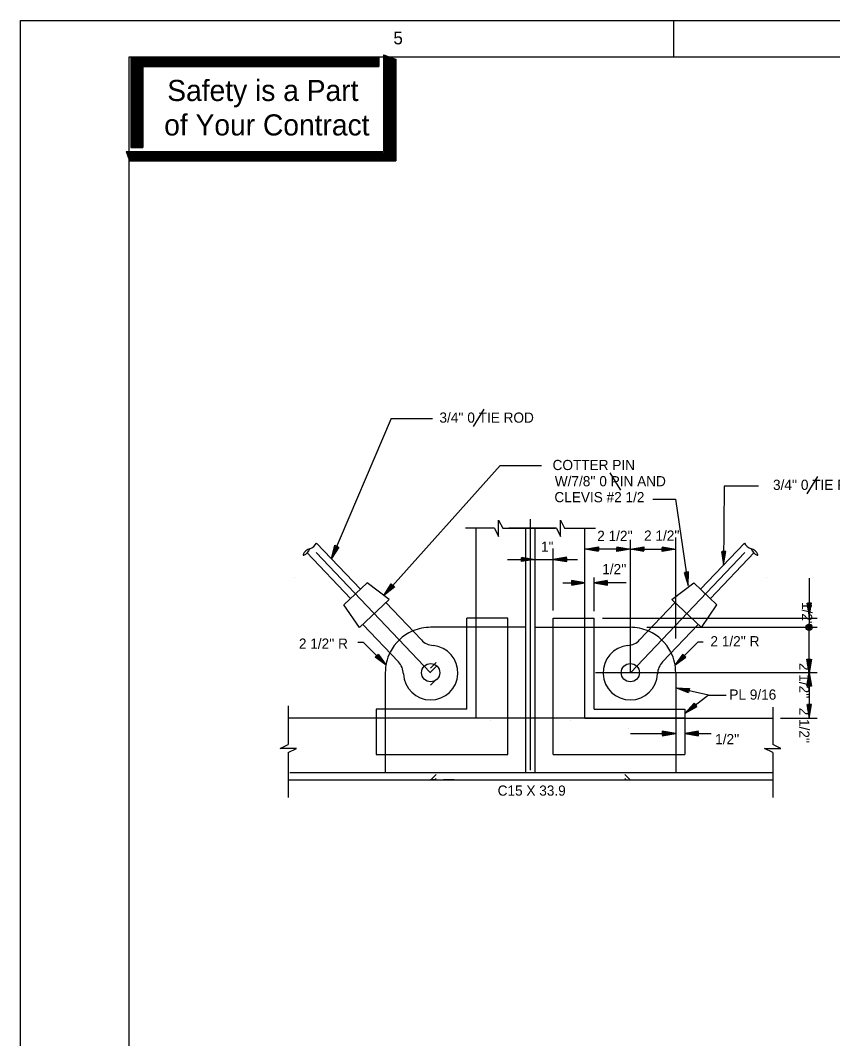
# Model space of a CAD drawing. Extents: x -0.4 to 13.5, y 0 to 9.5.
# Drawn here: x 0.125 to 3.853, y 4.787 to 9.458 of the extents above; entities that cross this region are included whole.
import ezdxf

# ---------------------------------------------------------------- set-up
doc = ezdxf.new("R2010")
doc.units = 0
for name, color, linetype in [('Level 1', 7, 'Continuous'), ('Level 13', 7, 'Continuous'), ('Level 25', 7, 'Continuous'), ('Level 3', 7, 'Continuous'), ('Level 50', 7, 'Continuous')]:
    doc.layers.add(name, color=color, linetype=linetype)

msp = doc.modelspace()

# ---------------------------------------------------------------- linework, layer by layer
at = {"layer": 'Level 1'}
for p, q in [((3.125, 9.2917), (3.125, 9.4583)), ((1.792, 9.3009), (1.792, 8.8562)), ((1.792, 9.3009), (1.8477, 9.2802)), ((1.7957, 9.2996), (1.7957, 8.8146)), ((1.8007, 9.2976), (1.8007, 8.8146)), ((0.632, 9.2886), (1.771, 9.2886)), ((0.632, 9.2886), (0.632, 8.8749)), ((0.632, 9.2832), (1.771, 9.2832)), ((0.632, 9.2782), (1.771, 9.2782)), ((0.632, 9.2729), (1.771, 9.2729)), ((0.632, 9.2676), (1.771, 9.2676)), ((0.632, 9.2626), (1.771, 9.2626)), ((0.632, 9.2572), (1.771, 9.2572)), ((0.632, 9.2522), (1.771, 9.2522)), ((0.6374, 9.2886), (0.6374, 8.8749)), ((0.6424, 9.2886), (0.6424, 8.8749)), ((0.6477, 9.2886), (0.6477, 8.8749)), ((0.6527, 9.2886), (0.6527, 8.8749)), ((0.658, 9.2886), (0.658, 8.8749)), ((0.6634, 9.2886), (0.6634, 8.8749)), ((0.6684, 9.2886), (0.6684, 8.8749)), ((0.6737, 9.2886), (0.6737, 8.8749)), ((0.679, 9.2886), (0.679, 8.8749)), ((0.684, 9.2886), (0.684, 8.8749)), ((1.771, 9.2886), (1.771, 9.2469)), ((1.806, 9.2956), (1.806, 8.8146)), ((1.8114, 9.2936), (1.8114, 8.8146)), ((1.8164, 9.2919), (1.8164, 8.8146)), ((1.8217, 9.2899), (1.8217, 8.8146)), ((1.8267, 9.2879), (1.8267, 8.8146)), ((1.832, 9.2859), (1.832, 8.8146)), ((1.8374, 9.2842), (1.8374, 8.8146)), ((1.8424, 9.2802), (1.8424, 8.8146)), ((1.8477, 9.2802), (1.8477, 8.8146)), ((0.6877, 9.2469), (1.771, 9.2469)), ((0.6877, 9.2469), (0.6877, 8.8749)), ((0.611, 8.8562), (1.792, 8.8562)), ((0.611, 8.8562), (0.6264, 8.8146)), ((0.613, 8.8509), (1.7957, 8.8509)), ((0.6147, 8.8459), (1.7957, 8.8459)), ((0.6167, 8.8406), (1.7957, 8.8406)), ((0.6187, 8.8352), (1.7957, 8.8352)), ((0.6207, 8.8302), (1.7957, 8.8302)), ((0.632, 8.8749), (0.6877, 8.8749)), ((0.6227, 8.8249), (1.7957, 8.8249)), ((0.6244, 8.8199), (1.7957, 8.8199)), ((0.6264, 8.8146), (1.8477, 8.8146)), ((2.2524, 7.6741), (2.2036, 7.5953)), ((2.8809, 7.3031), (2.8322, 7.3819)), ((3.7834, 7.3656), (3.7346, 7.2869)), ((2.3017, 7.1287), (2.1685, 7.1287)), ((2.3391, 7.1287), (2.5811, 7.1287)), ((2.5854, 7.1287), (2.3675, 7.1287)), ((2.6228, 7.1287), (2.7645, 7.1287)), ((2.9248, 7.0326), (2.7165, 7.0326)), ((2.9248, 7.0326), (3.1332, 7.0326)), ((2.3611, 6.9854), (2.4873, 6.9854)), ((2.4873, 6.9854), (2.6825, 6.9854)), ((2.6143, 6.8781), (2.7165, 6.8781)), ((2.9055, 6.8781), (2.7582, 6.8781)), ((2.7971, 6.7156), (3.7825, 6.7156)), ((2.9999, 6.674), (3.7825, 6.674)), ((3.7825, 6.4656), (2.7645, 6.4656)), ((3.6135, 6.2573), (3.7825, 6.2573)), ((2.9248, 6.1866), (3.1332, 6.1866)), ((3.1748, 6.1866), (3.2959, 6.1866))]:
    msp.add_line(p, q, dxfattribs=at)
for points in [[(0.125, 9.4583), (13.4583, 9.4583), (13.4583, 0.125), (0.125, 0.125)], [(0.625, 9.2917), (13.2917, 9.2917), (13.2917, 0.2917), (0.625, 0.2917)]]:
    msp.add_lwpolyline(points, close=True, dxfattribs=at)
at = {"layer": 'Level 13'}
for points in [[(2.3017, 7.1287), (2.3203, 7.0912), (2.3203, 7.1661), (2.3391, 7.1287)], [(2.5854, 7.1287), (2.604, 7.0912), (2.604, 7.1661), (2.6228, 7.1287)], [(1.3548, 6.0988), (1.3923, 6.1174), (1.3174, 6.1174), (1.3548, 6.1361)], [(3.5782, 6.0988), (3.5407, 6.1174), (3.6156, 6.1174), (3.5782, 6.1361)]]:
    msp.add_lwpolyline(points, dxfattribs=at)
for centre, radius, start, end in [((1.4387, 7.083), 0.051, 287.0106, 333.8095), ((3.4943, 7.083), 0.051, 206.1905, 252.9894), ((1.4249, 7.0069), 0.0025, 153.8112, 293.4241), ((1.4685, 6.9855), 0.051, 107.0106, 153.8112), ((1.4056, 7.0515), 0.051, 293.4241, 340.2247), ((3.5274, 7.0515), 0.051, 199.7753, 246.5759), ((3.4645, 6.9855), 0.051, 26.1888, 72.9894), ((3.5081, 7.0069), 0.0025, 246.5759, 26.1888)]:
    msp.add_arc(centre, radius, start, end, dxfattribs=at)
at = {"layer": 'Level 25'}
for p, q in [((1.8277, 7.6314), (1.5527, 6.9889)), ((1.8277, 7.6314), (2.0174, 7.6314)), ((2.3278, 7.4155), (1.7938, 6.8196)), ((2.3278, 7.4155), (2.5175, 7.4155)), ((2.4665, 6.0189), (2.4665, 7.1693)), ((2.2165, 6.2573), (2.2165, 7.1287)), ((2.4457, 6.0073), (2.4457, 7.1287)), ((2.4873, 6.0073), (2.4873, 7.1287)), ((2.7165, 6.2573), (2.7165, 7.1287)), ((1.6859, 6.8492), (1.4845, 7.0605)), ((2.9248, 6.4656), (2.9248, 7.0754)), ((3.1332, 6.6225), (3.1332, 7.0853)), ((3.2471, 6.8492), (3.4485, 7.0605)), ((1.6406, 6.8061), (1.4393, 7.0174)), ((2.0082, 6.4656), (1.4824, 7.0174)), ((2.5707, 6.7506), (2.5707, 7.0357)), ((2.9248, 6.4656), (3.4506, 7.0174)), ((3.2924, 6.8061), (3.4937, 7.0174)), ((1.3832, 6.9021), (1.3832, 6.9021)), ((1.7161, 6.8779), (1.6105, 6.7773)), ((1.8174, 6.8018), (1.7161, 6.8779)), ((2.7582, 6.7475), (2.7582, 6.9024)), ((3.1156, 6.8018), (3.2169, 6.8779)), ((3.2169, 6.8779), (3.3225, 6.7773)), ((3.5498, 6.9021), (3.5498, 6.9021)), ((3.7455, 6.8996), (3.7455, 6.6913)), ((1.6816, 6.6725), (1.6105, 6.7773)), ((1.8174, 6.8018), (1.6816, 6.6725)), ((1.9659, 6.6157), (1.8023, 6.7874)), ((2.9671, 6.6157), (3.1307, 6.7874)), ((3.1156, 6.8018), (3.2514, 6.6725)), ((3.2514, 6.6725), (3.3225, 6.7773)), ((1.8603, 6.5151), (1.6967, 6.6868)), ((2.1748, 6.299), (2.1748, 6.7156)), ((2.2165, 6.7156), (2.1748, 6.7156)), ((2.3623, 6.7156), (2.2165, 6.7156)), ((2.3623, 6.0906), (2.3623, 6.7156)), ((2.5707, 6.0906), (2.5707, 6.7156)), ((2.5707, 6.7156), (2.7165, 6.7156)), ((2.7165, 6.7156), (2.7582, 6.7156)), ((2.7582, 6.299), (2.7582, 6.7156)), ((3.0727, 6.5151), (3.2363, 6.6868)), ((3.7455, 6.483), (3.7455, 6.6913)), ((2.2165, 6.674), (2.0082, 6.674)), ((2.1748, 6.674), (2.0082, 6.674)), ((2.1748, 6.674), (2.1748, 6.674)), ((2.4457, 6.674), (2.1748, 6.674)), ((2.4873, 6.674), (2.7582, 6.674)), ((2.7165, 6.674), (2.9248, 6.674)), ((2.7582, 6.674), (2.7582, 6.674)), ((2.7582, 6.674), (2.9248, 6.674)), ((2.0343, 6.5128), (2.0082, 6.4868)), ((2.0343, 6.494), (2.0082, 6.4679)), ((1.7998, 6.4656), (1.7998, 6.299)), ((3.1332, 6.4656), (3.1332, 6.299)), ((3.7455, 6.483), (3.7455, 6.2573)), ((2.0343, 6.4351), (2.0082, 6.409)), ((3.2831, 6.3628), (3.1332, 6.3963)), ((3.2831, 6.3628), (3.1748, 6.2787)), ((3.2831, 6.3628), (3.3651, 6.3628)), ((1.3548, 6.3131), (1.3548, 6.1361)), ((3.5782, 6.3075), (3.5782, 6.1361)), ((2.1748, 6.299), (1.7582, 6.299)), ((1.7582, 6.299), (1.7582, 6.2503)), ((1.7998, 6.299), (1.7998, 6.0073)), ((2.7582, 6.299), (3.1748, 6.299)), ((3.1332, 6.299), (3.1332, 6.0073)), ((3.1748, 6.299), (3.1748, 6.2535)), ((2.7165, 6.2573), (1.3548, 6.2573)), ((2.2165, 6.2573), (1.7582, 6.2573)), ((1.7582, 6.2503), (1.7582, 6.0906)), ((2.2846, 6.2465), (2.2846, 6.2465)), ((2.6484, 6.2465), (2.6484, 6.2465)), ((2.7165, 6.2573), (3.5782, 6.2573)), ((3.1748, 6.2573), (2.7165, 6.2573)), ((3.1748, 6.2535), (3.1748, 6.0906)), ((2.9171, 6.2079), (2.9171, 6.2079)), ((1.3548, 6.0988), (1.3548, 5.8928)), ((1.7582, 6.0906), (2.3623, 6.0906)), ((2.5707, 6.0906), (3.1748, 6.0906)), ((3.5782, 6.0988), (3.5782, 5.8928)), ((1.3621, 6.0073), (3.5782, 6.0073)), ((2.0343, 5.9989), (2.0087, 5.9734)), ((2.0343, 5.9801), (2.0276, 5.9734)), ((2.8988, 5.9989), (2.9243, 5.9734)), ((2.8988, 5.9801), (2.9054, 5.9734)), ((1.3548, 5.974), (3.5782, 5.974)), ((2.0343, 5.9734), (2.0082, 5.9734)), ((2.1165, 5.9734), (2.0666, 5.9734)), ((2.1029, 5.9734), (2.1029, 5.9734)), ((2.8165, 5.9734), (2.8665, 5.9734)), ((2.8301, 5.9734), (2.8301, 5.9734)), ((2.8988, 5.9734), (2.9248, 5.9734))]:
    msp.add_line(p, q, dxfattribs=at)
for centre in [(2.0082, 6.4656), (2.9248, 6.4656)]:
    msp.add_circle(centre, 0.0417, dxfattribs=at)
for centre, radius, start, end in [((2.0082, 6.4656), 0.2083, 113.9464, 153.1723), ((2.0082, 6.4656), 0.2083, 90, 113.2322), ((2.9248, 6.4656), 0.2083, 66.7678, 90), ((2.9248, 6.4656), 0.2083, 26.8277, 66.0536), ((2.0082, 6.4656), 0.125, 182.1999, 85.0192), ((2.0263, 6.6732), 0.0833, 223.6094, 265.0192), ((2.9248, 6.4656), 0.125, 94.9808, 357.8001), ((2.9068, 6.6732), 0.0833, 274.9808, 316.3906), ((2.0082, 6.4656), 0.2083, 153.5287, 180), ((2.9248, 6.4656), 0.2083, 0, 26.4713), ((1.8, 6.4576), 0.0833, 2.1999, 43.6109), ((3.133, 6.4576), 0.0833, 136.3891, 177.8001)]:
    msp.add_arc(centre, radius, start, end, dxfattribs=at)
at = {"layer": 'Level 3'}
for p, q in [((3.3527, 6.9772), (3.3527, 6.9772)), ((3.3526, 6.9598), (3.3526, 6.9598)), ((3.188, 6.8824), (3.188, 6.8824)), ((3.1905, 6.8653), (3.1905, 6.8653)), ((1.7922, 6.5119), (1.7922, 6.5119)), ((1.8044, 6.4996), (1.8044, 6.4996)), ((3.1286, 6.4996), (3.1286, 6.4996)), ((3.1408, 6.5119), (3.1408, 6.5119))]:
    msp.add_line(p, q, dxfattribs=at)
for points in [[(3.5129, 7.3221), (3.3553, 7.3221), (3.3526, 6.9598)], [(3.0285, 7.2619), (3.1317, 7.2619), (3.1905, 6.8653)], [(3.3427, 7.0222), (3.3526, 6.9598), (3.3634, 7.0221), (3.3457, 7.0222), (3.3527, 6.9772), (3.36, 7.0194), (3.3487, 7.0195), (3.3528, 6.9938), (3.3567, 7.0168), (3.352, 7.0168), (3.353, 7.0112)], [(3.1712, 6.9254), (3.1905, 6.8653), (3.1916, 6.9284), (3.1741, 6.9258), (3.188, 6.8824), (3.1887, 6.9253), (3.1775, 6.9236), (3.1856, 6.8989), (3.1858, 6.9222), (3.1812, 6.9215), (3.183, 6.916)], [(1.6743, 6.605), (1.6991, 6.605), (1.8044, 6.4996)], [(3.2587, 6.605), (3.2339, 6.605), (3.1286, 6.4996)], [(1.7677, 6.551), (1.8044, 6.4996), (1.7531, 6.5364), (1.7656, 6.5489), (1.7922, 6.5119), (1.7573, 6.5368), (1.7653, 6.5449), (1.7804, 6.5236), (1.7615, 6.5373), (1.7648, 6.5406), (1.7681, 6.5359)], [(3.1653, 6.551), (3.1286, 6.4996), (3.18, 6.5364), (3.1675, 6.5489), (3.1408, 6.5119), (3.1757, 6.5368), (3.1677, 6.5449), (3.1526, 6.5236), (3.1715, 6.5373), (3.1682, 6.5406), (3.1649, 6.5359)]]:
    msp.add_lwpolyline(points, dxfattribs=at)
at = {"layer": 'Level 50'}
for p, q in [((2.7165, 7.0326), (2.7165, 7.0326)), ((2.7338, 7.0326), (2.7338, 7.0326)), ((2.9075, 7.0326), (2.9075, 7.0326)), ((2.9248, 7.0326), (2.9248, 7.0326)), ((2.9248, 7.0326), (2.9248, 7.0326)), ((2.9422, 7.0326), (2.9422, 7.0326)), ((3.1158, 7.0326), (3.1158, 7.0326)), ((3.1332, 7.0326), (3.1332, 7.0326)), ((1.5527, 6.9889), (1.5527, 6.9889)), ((1.5595, 7.0049), (1.5595, 7.0049)), ((2.47, 6.9854), (2.47, 6.9854)), ((2.4873, 6.9854), (2.4873, 6.9854)), ((2.5707, 6.9854), (2.5707, 6.9854)), ((2.588, 6.9854), (2.588, 6.9854)), ((2.6992, 6.8781), (2.6992, 6.8781)), ((2.7165, 6.8781), (2.7165, 6.8781)), ((2.7582, 6.8781), (2.7582, 6.8781)), ((2.7755, 6.8781), (2.7755, 6.8781)), ((1.8054, 6.8325), (1.8054, 6.8325)), ((1.7938, 6.8196), (1.7938, 6.8196)), ((3.7455, 6.7392), (3.7455, 6.7392)), ((3.7455, 6.7219), (3.7455, 6.7219)), ((3.7455, 6.483), (3.7455, 6.483)), ((3.7455, 6.4656), (3.7455, 6.4656)), ((3.7455, 6.4656), (3.7455, 6.4656)), ((3.7455, 6.4483), (3.7455, 6.4483)), ((3.1332, 6.3963), (3.1332, 6.3963)), ((3.1501, 6.3925), (3.1501, 6.3925)), ((3.1748, 6.2787), (3.1748, 6.2787)), ((3.1885, 6.2893), (3.1885, 6.2893)), ((3.7455, 6.2746), (3.7455, 6.2746)), ((3.7455, 6.2573), (3.7455, 6.2573)), ((3.1158, 6.1866), (3.1158, 6.1866)), ((3.1332, 6.1866), (3.1332, 6.1866)), ((3.1748, 6.1866), (3.1748, 6.1866)), ((3.1922, 6.1866), (3.1922, 6.1866))]:
    msp.add_line(p, q, dxfattribs=at)
for points in [[(1.5867, 7.0422), (1.5527, 6.9889), (1.5677, 7.0503), (1.584, 7.0434), (1.5595, 7.0049), (1.5697, 7.0465), (1.5802, 7.0421), (1.5661, 7.0202), (1.5718, 7.0428), (1.576, 7.0409), (1.5729, 7.0361)], [(2.7788, 7.0223), (2.7165, 7.0326), (2.7788, 7.0429), (2.7788, 7.0253), (2.7338, 7.0326), (2.7762, 7.0396), (2.7762, 7.0283), (2.7505, 7.0326), (2.7735, 7.0363), (2.7735, 7.0316), (2.7678, 7.0326)], [(2.8625, 7.0429), (2.9248, 7.0326), (2.8625, 7.0223), (2.8625, 7.0399), (2.9075, 7.0326), (2.8652, 7.0256), (2.8652, 7.0369), (2.8908, 7.0326), (2.8678, 7.0289), (2.8678, 7.0336), (2.8735, 7.0326)], [(2.9872, 7.0223), (2.9248, 7.0326), (2.9872, 7.0429), (2.9872, 7.0253), (2.9422, 7.0326), (2.9845, 7.0396), (2.9845, 7.0283), (2.9588, 7.0326), (2.9818, 7.0363), (2.9818, 7.0316), (2.9762, 7.0326)], [(3.0708, 7.0429), (3.1332, 7.0326), (3.0708, 7.0223), (3.0708, 7.0399), (3.1158, 7.0326), (3.0735, 7.0256), (3.0735, 7.0369), (3.0992, 7.0326), (3.0762, 7.0289), (3.0762, 7.0336), (3.0818, 7.0326)], [(2.425, 6.9958), (2.4873, 6.9854), (2.425, 6.9751), (2.425, 6.9928), (2.47, 6.9854), (2.4277, 6.9784), (2.4277, 6.9898), (2.4533, 6.9854), (2.4303, 6.9818), (2.4303, 6.9864), (2.436, 6.9854)], [(2.633, 6.9958), (2.5707, 6.9854), (2.633, 6.9751), (2.633, 6.9928), (2.588, 6.9854), (2.6303, 6.9784), (2.6303, 6.9898), (2.6047, 6.9854), (2.6277, 6.9818), (2.6277, 6.9864), (2.622, 6.9854)], [(1.8431, 6.8591), (1.7938, 6.8196), (1.8277, 6.8729), (1.8408, 6.8611), (1.8054, 6.8325), (1.8284, 6.8687), (1.8368, 6.8611), (1.8165, 6.8449), (1.8291, 6.8645), (1.8326, 6.8613), (1.828, 6.8578)], [(2.6542, 6.8677), (2.7165, 6.8781), (2.6542, 6.8884), (2.6542, 6.8707), (2.6992, 6.8781), (2.6568, 6.8851), (2.6568, 6.8737), (2.6825, 6.8781), (2.6595, 6.8817), (2.6595, 6.8771), (2.6652, 6.8781)], [(2.8205, 6.8884), (2.7582, 6.8781), (2.8205, 6.8677), (2.8205, 6.8854), (2.7755, 6.8781), (2.8178, 6.8711), (2.8178, 6.8824), (2.7922, 6.8781), (2.8152, 6.8744), (2.8152, 6.8791), (2.8095, 6.8781)], [(3.7352, 6.7842), (3.7455, 6.7219), (3.7559, 6.7842), (3.7382, 6.7842), (3.7455, 6.7392), (3.7525, 6.7815), (3.7412, 6.7815), (3.7455, 6.7559), (3.7492, 6.7789), (3.7445, 6.7789), (3.7455, 6.7732)], [(3.7559, 6.528), (3.7455, 6.4656), (3.7352, 6.528), (3.7529, 6.528), (3.7455, 6.483), (3.7385, 6.5253), (3.7499, 6.5253), (3.7455, 6.4996), (3.7419, 6.5226), (3.7465, 6.5226), (3.7455, 6.517)], [(3.7352, 6.4033), (3.7455, 6.4656), (3.7559, 6.4033), (3.7382, 6.4033), (3.7455, 6.4483), (3.7525, 6.406), (3.7412, 6.406), (3.7455, 6.4316), (3.7492, 6.4086), (3.7445, 6.4086), (3.7455, 6.4143)], [(3.1918, 6.3726), (3.1332, 6.3963), (3.1963, 6.3928), (3.1924, 6.3755), (3.1501, 6.3925), (3.1929, 6.3901), (3.1905, 6.379), (3.1664, 6.3889), (3.1896, 6.3874), (3.1886, 6.3829), (3.1833, 6.3851)], [(3.2304, 6.3088), (3.1748, 6.2787), (3.2177, 6.3251), (3.2286, 6.3111), (3.1885, 6.2893), (3.2177, 6.3208), (3.2246, 6.3119), (3.2017, 6.2996), (3.2176, 6.3166), (3.2205, 6.3129), (3.2154, 6.3102)], [(3.7352, 6.3196), (3.7455, 6.2573), (3.7559, 6.3196), (3.7382, 6.3196), (3.7455, 6.2746), (3.7525, 6.317), (3.7412, 6.317), (3.7455, 6.2913), (3.7492, 6.3143), (3.7445, 6.3143), (3.7455, 6.3086)], [(3.0708, 6.1763), (3.1332, 6.1866), (3.0708, 6.1969), (3.0708, 6.1793), (3.1158, 6.1866), (3.0735, 6.1936), (3.0735, 6.1823), (3.0992, 6.1866), (3.0762, 6.1903), (3.0762, 6.1856), (3.0818, 6.1866)], [(3.2372, 6.1969), (3.1748, 6.1866), (3.2372, 6.1763), (3.2372, 6.1939), (3.1922, 6.1866), (3.2345, 6.1796), (3.2345, 6.1909), (3.2088, 6.1866), (3.2318, 6.1829), (3.2318, 6.1876), (3.2262, 6.1866)]]:
    msp.add_lwpolyline(points, dxfattribs=at)
for radius in [0.0141, 0.00879, 0.00352]:
    msp.add_circle((3.7455, 6.674), radius, dxfattribs=at)

# ---------------------------------------------------------------- texts
at = {"layer": 'Level 1'}
for s, height, p in [('5', 0.0584, (1.8373, 9.3483)), ('Safety is a Part', 0.096792, (0.7992, 9.0883)), ('of Your Contract', 0.096792, (0.7852, 8.9303)), ("3/4'' 0 TIE ROD", 0.046698, (2.0486, 7.6126)), ('COTTER PIN', 0.0467, (2.5679, 7.3952)), ("W/7/8'' 0 PIN AND", 0.046698, (2.5782, 7.3208)), ("3/4'' 0 TIE ROD", 0.046698, (3.5796, 7.3042)), ('CLEVIS #2 1/2', 0.046698, (2.5763, 7.2476)), ("2 1/2''", 0.0467, (2.7728, 7.07)), ("2 1/2''", 0.0467, (2.988, 7.0713)), ("2 1/2'' R", 0.0467, (3.2925, 6.5866)), ("2 1/2'' R", 0.0467, (1.4034, 6.5757)), ('PL 9/16', 0.0467, (3.3793, 6.3419))]:
    msp.add_text(s, height=height, dxfattribs=at).set_placement(p)
for p in [(3.7001, 6.5108), (3.7001, 6.3052)]:
    msp.add_text("2 1/2''", height=0.0467, rotation=270, dxfattribs=at).set_placement(p)
at = {"layer": 'Level 25'}
for s, p in [('1"', (2.5149, 7.0204)), ("1/2''", (2.7958, 6.9176)), ("1/2''", (3.3142, 6.1375)), ('C15 X 33.9', (2.3158, 5.9015))]:
    msp.add_text(s, height=0.0467, dxfattribs=at).set_placement(p)
msp.add_text("1/2''", height=0.0467, rotation=270, dxfattribs=at).set_placement((3.7125, 6.7903))

doc.saveas('drawing.dxf')
